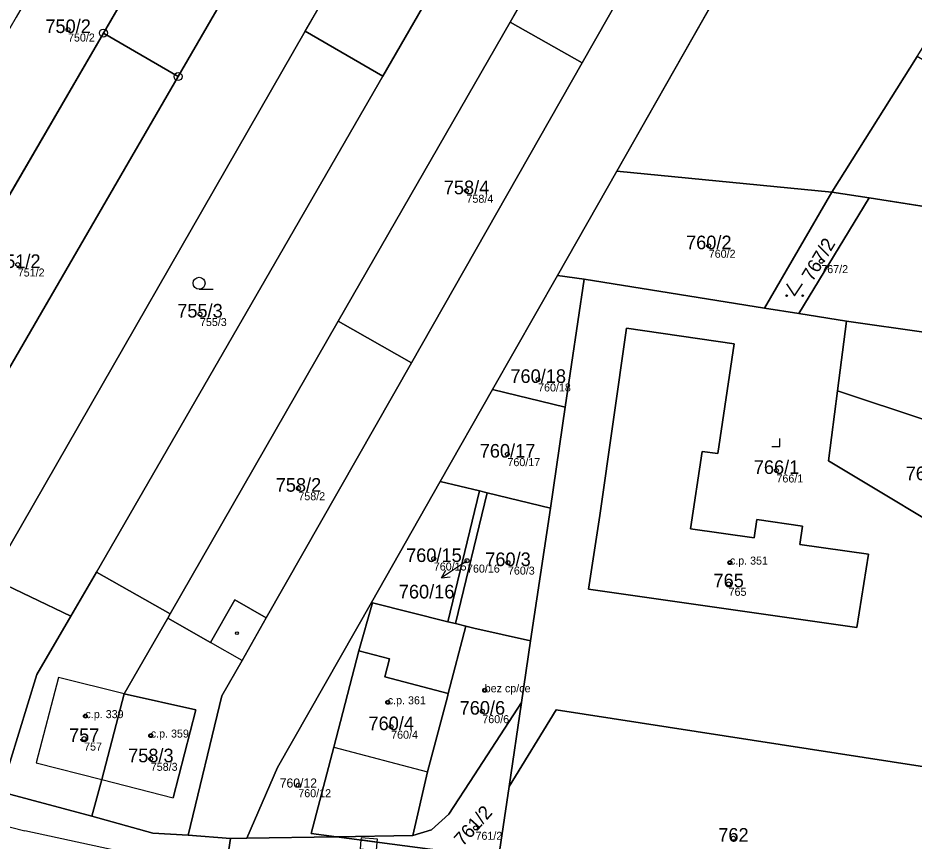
# Model space of a CAD drawing. Extents: x -603967 to -594699, y -1179315 to -1165625.
# Drawn here: x -598099.7 to -597987.7, y -1172272.3 to -1172169.5 of the extents above; entities that cross this region are included whole.
import ezdxf

# ---------------------------------------------------------------- set-up
doc = ezdxf.new("R2010")
doc.units = 0
for name, color, linetype in [('Definiční body', 7, 'Continuous'), ('Hranice parcel', 7, 'Continuous'), ('Parcelní čísla', 7, 'Continuous'), ('Polygon budovy', 7, 'Continuous'), ('Polygon parcely', 7, 'Continuous'), ('Pop  PČ popisy', 7, 'Continuous'), ('Vnitřní kresba', 7, 'Continuous'), ('Věcná břemena k části', 7, 'Continuous'), ('Značky bodu BP', 7, 'Continuous'), ('Značky budov', 7, 'Continuous'), ('Značky kultur', 7, 'Continuous')]:
    doc.layers.add(name, color=color, linetype=linetype)

msp = doc.modelspace()

# ---------------------------------------------------------------- linework, layer by layer
at = {"layer": 'Definiční body'}
for centre in [(-598093.44, -1172170.91994), (-598043.66, -1172191.05994), (-598013.39, -1172197.92994), (-598099.72, -1172200.26994), (-597999.33, -1172199.84994), (-598076.96, -1172206.45994), (-598034.71, -1172214.62994), (-598038.54, -1172223.95994), (-598004.93, -1172225.99994), (-598064.66, -1172228.21994), (-598047.74, -1172236.99994), (-598043.59, -1172237.25994), (-598038.48, -1172237.50994), (-598010.75, -1172237.49994), (-598010.91, -1172240.15994), (-598041.38, -1172253.44994), (-598053.49, -1172254.94994), (-598091.26, -1172256.67994), (-598041.68, -1172256.06994), (-598053.07, -1172258.00994), (-598091.43, -1172259.48994), (-598083.1, -1172259.10994), (-598083.1, -1172262.01994), (-598064.67, -1172265.31994), (-598042.53, -1172270.63994), (-598010.31, -1172271.93994)]:
    msp.add_circle(centre, 0.25, dxfattribs=at)
at = {"layer": 'Hranice parcel'}
for p, q in [((-598089.02, -1172171.35), (-598041.74, -1172089.99)), ((-598031.05, -1172092.86), (-598079.69, -1172176.78)), ((-598063.8, -1172171.13), (-598020.26, -1172095.37)), ((-598054.1, -1172176.74), (-598008.71, -1172098.13)), ((-598038.22, -1172169.98), (-597998.29, -1172100.64)), ((-598029.22, -1172175.08), (-597988.37, -1172103.28)), ((-598024.89, -1172188.58), (-597977.95, -1172106.04)), ((-598059.71, -1172207.33), (-598038.22, -1172169.98)), ((-598038.22, -1172169.98), (-598029.22, -1172175.08)), ((-598113.19, -1172212.94), (-598089.02, -1172171.35)), ((-598102.03, -1172237.66), (-598063.8, -1172171.13)), ((-598089.02, -1172171.35), (-598079.69, -1172176.78)), ((-598063.8, -1172171.13), (-598054.1, -1172176.74)), ((-597998, -1172191.21), (-597987.33, -1172174.26)), ((-598029.22, -1172175.08), (-598050.53, -1172212.53)), ((-598079.69, -1172176.78), (-598111.73, -1172232.07)), ((-598054.1, -1172176.74), (-598089.89, -1172238.69)), ((-598032.3, -1172201.62), (-598024.89, -1172188.58)), ((-598024.89, -1172188.58), (-597998, -1172191.21)), ((-598006.42, -1172205.7), (-597998, -1172191.21)), ((-597993.35, -1172191.94), (-597998, -1172191.21)), ((-598002.14, -1172206.39), (-597993.35, -1172191.94)), ((-597972.54, -1172195.22), (-597993.35, -1172191.94)), ((-598040.4, -1172215.87), (-598032.3, -1172201.62)), ((-598032.3, -1172201.62), (-598028.95, -1172202.1)), ((-598028.95, -1172202.1), (-598031.31, -1172218.07)), ((-598028.95, -1172202.1), (-598006.42, -1172205.7)), ((-598006.42, -1172205.7), (-598002.14, -1172206.39)), ((-598002.14, -1172206.39), (-597996.18, -1172207.34)), ((-598080.66, -1172243.92), (-598059.71, -1172207.33)), ((-598050.53, -1172212.53), (-598059.71, -1172207.33)), ((-597997.29, -1172216.06), (-597996.18, -1172207.34)), ((-598068.67, -1172244.4), (-598050.53, -1172212.53)), ((-598046.94, -1172227.36), (-598040.4, -1172215.87)), ((-598031.31, -1172218.07), (-598040.4, -1172215.87)), ((-597975.12, -1172223.43), (-597997.29, -1172216.06)), ((-598031.31, -1172218.07), (-598033.18, -1172230.68)), ((-598055.53, -1172242.48), (-598046.94, -1172227.36)), ((-598042.05, -1172228.54), (-598046.94, -1172227.36)), ((-598045.99, -1172244.88), (-598042.05, -1172228.54)), ((-598041.07, -1172228.78), (-598045.02, -1172245.12)), ((-598041.07, -1172228.78), (-598042.05, -1172228.54)), ((-598033.18, -1172230.68), (-598041.07, -1172228.78)), ((-598035.64, -1172247.28), (-598033.18, -1172230.68)), ((-598093.1, -1172244.2), (-598103.2, -1172239.38)), ((-598093.1, -1172244.2), (-598089.89, -1172238.69)), ((-598089.89, -1172238.69), (-598080.66, -1172243.92)), ((-598067.25, -1172263.09), (-598055.53, -1172242.48)), ((-598055.41, -1172242.51), (-598057.09, -1172248.51)), ((-598055.41, -1172242.51), (-598055.53, -1172242.48)), ((-598045.99, -1172244.88), (-598055.41, -1172242.51)), ((-598080.66, -1172243.92), (-598080.96, -1172244.44)), ((-598097.34, -1172251.48), (-598093.1, -1172244.2)), ((-598080.96, -1172244.44), (-598086.44, -1172253.89)), ((-598045.02, -1172245.12), (-598045.99, -1172244.88)), ((-598045.02, -1172245.12), (-598043.72, -1172245.45)), ((-598035.64, -1172247.28), (-598036.78, -1172254.99)), ((-598057.09, -1172248.51), (-598060.23, -1172260.57)), ((-598101.84, -1172266.14), (-598097.34, -1172251.48)), ((-598036.78, -1172254.99), (-598042.64, -1172264.03)), ((-598038.34, -1172265.49), (-598036.78, -1172254.99)), ((-598071.11, -1172271.92), (-598067.25, -1172263.09)), ((-598050.35, -1172271.6), (-598048.51, -1172263.64)), ((-598090.48, -1172269.19), (-598101.84, -1172266.14)), ((-598039.66, -1172274.43), (-598038.34, -1172265.49)), ((-598090.48, -1172269.19), (-598082.86, -1172271.28)), ((-598082.86, -1172271.28), (-598078.41, -1172271.53)), ((-598078.41, -1172271.53), (-598073.16, -1172271.95)), ((-598073.16, -1172271.95), (-598071.11, -1172271.92)), ((-598059.89, -1172271.75), (-598071.11, -1172271.92)), ((-598059.89, -1172271.75), (-598050.35, -1172271.6)), ((-598039.66, -1172274.43), (-598059.89, -1172271.75))]:
    msp.add_line(p, q, dxfattribs=at)
for points in [[(-598028.42, -1172240.8), (-598026.98, -1172231.6), (-598023.66, -1172208.21), (-598010.23, -1172210.19), (-598012.26, -1172223.89), (-598014.23, -1172223.6)], [(-597996.18, -1172207.34), (-597976.28, -1172210.18), (-597955.84, -1172213.01)], [(-597979.58, -1172236.11), (-597998.41, -1172224.79), (-597997.29, -1172216.06)], [(-598014.23, -1172223.6), (-598015.68, -1172233.3), (-598007.71, -1172234.42), (-598007.39, -1172232.13), (-598001.67, -1172232.94), (-598002, -1172235.22), (-597993.44, -1172236.43), (-597994.9, -1172245.61), (-598028.42, -1172240.8)], [(-598080.96, -1172244.44), (-598075.62, -1172247.48), (-598072.59, -1172242.16), (-598068.67, -1172244.4)], [(-598078.41, -1172271.53), (-598074.21, -1172254.14), (-598071.69, -1172249.71), (-598068.67, -1172244.4)], [(-598048.51, -1172263.64), (-598046.03, -1172254.27), (-598045.93, -1172253.84), (-598043.72, -1172245.45)], [(-598043.72, -1172245.45), (-598042.73, -1172245.7), (-598035.64, -1172247.28)], [(-598086.44, -1172253.89), (-598089.23, -1172264.61), (-598090.48, -1172269.19)], [(-597983.49, -1172263.46), (-598032.47, -1172255.88), (-598038.34, -1172265.49)], [(-598060.23, -1172260.57), (-598063.08, -1172271.35), (-598059.89, -1172271.75)], [(-598042.64, -1172264.03), (-598045.87, -1172268.94), (-598048.03, -1172270.89), (-598050.35, -1172271.6)], [(-598073.16, -1172271.95), (-598073.47, -1172274.19), (-598070.89, -1172276.93), (-598057.82, -1172275.89), (-598050.62, -1172276.09), (-598046.74, -1172275.42)]]:
    msp.add_lwpolyline(points, dxfattribs=at)
at = {"layer": 'Polygon budovy'}
for points in [[(-598026.98, -1172231.6), (-598028.42, -1172240.8), (-597994.9, -1172245.61), (-597993.44, -1172236.43), (-598002, -1172235.22), (-598001.67, -1172232.94), (-598007.39, -1172232.13), (-598007.71, -1172234.42), (-598015.68, -1172233.3), (-598014.23, -1172223.6), (-598012.26, -1172223.89), (-598010.23, -1172210.19), (-598023.66, -1172208.21)], [(-598043.72, -1172245.45), (-598045.93, -1172253.84), (-598046.03, -1172254.27), (-598048.51, -1172263.64), (-598050.35, -1172271.6), (-598048.03, -1172270.89), (-598045.87, -1172268.94), (-598042.64, -1172264.03), (-598036.78, -1172254.99), (-598035.64, -1172247.28), (-598042.73, -1172245.7)], [(-598057.09, -1172248.51), (-598060.23, -1172260.57), (-598048.51, -1172263.64), (-598046.03, -1172254.27), (-598045.93, -1172253.84), (-598053.84, -1172251.76), (-598053.28, -1172249.51)], [(-598094.64, -1172251.86), (-598097.43, -1172262.52), (-598089.23, -1172264.61), (-598086.44, -1172253.89)], [(-598089.23, -1172264.61), (-598080.32, -1172266.9), (-598077.46, -1172255.91), (-598086.44, -1172253.89)]]:
    msp.add_lwpolyline(points, close=True, dxfattribs=at)
at = {"layer": 'Polygon parcely'}
for points in [[(-598059.98, -1172100.28), (-598067.04, -1172112.5), (-598069.12, -1172116.1), (-598099.9, -1172169.36), (-598122.69, -1172208.79), (-598113.19, -1172212.94), (-598089.02, -1172171.35), (-598041.74, -1172089.99), (-598052.53, -1172087.39)], [(-598079.69, -1172176.78), (-598031.05, -1172092.86), (-598041.74, -1172089.99), (-598089.02, -1172171.35)], [(-598020.26, -1172095.37), (-598031.05, -1172092.86), (-598079.69, -1172176.78), (-598111.73, -1172232.07), (-598107.49, -1172234.38), (-598102.03, -1172237.66), (-598063.8, -1172171.13)], [(-598008.71, -1172098.13), (-598020.26, -1172095.37), (-598063.8, -1172171.13), (-598054.1, -1172176.74)], [(-598008.71, -1172098.13), (-598054.1, -1172176.74), (-598089.89, -1172238.69), (-598080.66, -1172243.92), (-598059.71, -1172207.33), (-598038.22, -1172169.98), (-597998.29, -1172100.64)], [(-598029.22, -1172175.08), (-597988.37, -1172103.28), (-597998.29, -1172100.64), (-598038.22, -1172169.98)], [(-597977.95, -1172106.04), (-597988.37, -1172103.28), (-598029.22, -1172175.08), (-598050.53, -1172212.53), (-598068.67, -1172244.4), (-598071.69, -1172249.71), (-598074.21, -1172254.14), (-598078.41, -1172271.53), (-598073.16, -1172271.95), (-598071.11, -1172271.92), (-598067.25, -1172263.09), (-598055.53, -1172242.48), (-598046.94, -1172227.36), (-598040.4, -1172215.87), (-598032.3, -1172201.62), (-598024.89, -1172188.58)], [(-597964.77, -1172138.05), (-597950.03, -1172113.6), (-597977.95, -1172106.04), (-598024.89, -1172188.58), (-597998, -1172191.21), (-597987.33, -1172174.26), (-597984.55, -1172169.83), (-597978.05, -1172159.64)], [(-598038.22, -1172169.98), (-598059.71, -1172207.33), (-598050.53, -1172212.53), (-598029.22, -1172175.08)], [(-598113.19, -1172212.94), (-598116.92, -1172219.55), (-598121.43, -1172227.12), (-598116.8, -1172229.12), (-598111.73, -1172232.07), (-598079.69, -1172176.78), (-598089.02, -1172171.35)], [(-598089.89, -1172238.69), (-598054.1, -1172176.74), (-598063.8, -1172171.13), (-598102.03, -1172237.66), (-598102.62, -1172238.6), (-598103.2, -1172239.38), (-598093.1, -1172244.2)], [(-597953.45, -1172191.33), (-597952.32, -1172182.74), (-597952.07, -1172180.42), (-597982.2, -1172177.32), (-597987.33, -1172174.26), (-597998, -1172191.21), (-597993.35, -1172191.94), (-597972.54, -1172195.22), (-597971.12, -1172183.2), (-597960.3, -1172184.48), (-597961.68, -1172196.64), (-597954.14, -1172197.63)], [(-598032.3, -1172201.62), (-598028.95, -1172202.1), (-598006.42, -1172205.7), (-597998, -1172191.21), (-598024.89, -1172188.58)], [(-597998, -1172191.21), (-598006.42, -1172205.7), (-598002.14, -1172206.39), (-597993.35, -1172191.94)], [(-597964.82, -1172208.2), (-597973.95, -1172207.12), (-597972.54, -1172195.22), (-597993.35, -1172191.94), (-598002.14, -1172206.39), (-597996.18, -1172207.34), (-597976.28, -1172210.18), (-597955.84, -1172213.01), (-597954.14, -1172197.63), (-597961.68, -1172196.64), (-597962.78, -1172205.93), (-597964.52, -1172205.72)], [(-598032.3, -1172201.62), (-598040.4, -1172215.87), (-598031.31, -1172218.07), (-598028.95, -1172202.1)], [(-598002.14, -1172206.39), (-598006.42, -1172205.7), (-598028.95, -1172202.1), (-598031.31, -1172218.07), (-598033.18, -1172230.68), (-598035.64, -1172247.28), (-598036.78, -1172254.99), (-598038.34, -1172265.49), (-598032.47, -1172255.88), (-597983.49, -1172263.46), (-597980.32, -1172241.29), (-597979.58, -1172236.11), (-597998.41, -1172224.79), (-597997.29, -1172216.06), (-597996.18, -1172207.34)], [(-598050.53, -1172212.53), (-598059.71, -1172207.33), (-598080.66, -1172243.92), (-598080.96, -1172244.44), (-598075.62, -1172247.48), (-598072.59, -1172242.16), (-598068.67, -1172244.4)], [(-598014.23, -1172223.6), (-598012.26, -1172223.89), (-598010.23, -1172210.19), (-598023.66, -1172208.21), (-598026.98, -1172231.6), (-598028.42, -1172240.8), (-597994.9, -1172245.61), (-597993.44, -1172236.43), (-598002, -1172235.22), (-598001.67, -1172232.94), (-598007.39, -1172232.13), (-598007.71, -1172234.42), (-598015.68, -1172233.3)], [(-598007.39, -1172232.13), (-598001.67, -1172232.94), (-598002, -1172235.22), (-597993.44, -1172236.43), (-597994.9, -1172245.61), (-598028.42, -1172240.8), (-598026.98, -1172231.6), (-598023.66, -1172208.21), (-598010.23, -1172210.19), (-598012.26, -1172223.89), (-598014.23, -1172223.6), (-598015.68, -1172233.3), (-598007.71, -1172234.42)], [(-597964.63, -1172224.94), (-597957.24, -1172226), (-597955.84, -1172213.01), (-597976.28, -1172210.18), (-597996.18, -1172207.34), (-597997.29, -1172216.06), (-597975.12, -1172223.43), (-597973.83, -1172214.15), (-597963.34, -1172215.61), (-597963.78, -1172218.82), (-597962.6, -1172218.99), (-597962.98, -1172221.7), (-597964.16, -1172221.58)], [(-598031.31, -1172218.07), (-598040.4, -1172215.87), (-598046.94, -1172227.36), (-598042.05, -1172228.54), (-598041.07, -1172228.78), (-598033.18, -1172230.68)], [(-597965.9, -1172234.19), (-597976.41, -1172232.72), (-597975.12, -1172223.43), (-597997.29, -1172216.06), (-597998.41, -1172224.79), (-597979.58, -1172236.11), (-597960.36, -1172247.21), (-597957.51, -1172228.47), (-597957.24, -1172226), (-597964.63, -1172224.94), (-597965.09, -1172228.26), (-597963.89, -1172228.43), (-597964.29, -1172231.15), (-597965.47, -1172231)], [(-598042.05, -1172228.54), (-598046.94, -1172227.36), (-598055.53, -1172242.48), (-598055.41, -1172242.51), (-598045.99, -1172244.88)], [(-598041.07, -1172228.78), (-598042.05, -1172228.54), (-598045.99, -1172244.88), (-598045.02, -1172245.12)], [(-598035.64, -1172247.28), (-598033.18, -1172230.68), (-598041.07, -1172228.78), (-598045.02, -1172245.12), (-598043.72, -1172245.45), (-598042.73, -1172245.7)], [(-598103.2, -1172239.38), (-598109.12, -1172248.1), (-598111.41, -1172258.89), (-598112.46, -1172263.54), (-598101.84, -1172266.14), (-598097.34, -1172251.48), (-598093.1, -1172244.2)], [(-598097.34, -1172251.48), (-598101.84, -1172266.14), (-598090.48, -1172269.19), (-598089.23, -1172264.61), (-598086.44, -1172253.89), (-598080.96, -1172244.44), (-598080.66, -1172243.92), (-598089.89, -1172238.69), (-598093.1, -1172244.2)], [(-598078.41, -1172271.53), (-598074.21, -1172254.14), (-598071.69, -1172249.71), (-598068.67, -1172244.4), (-598072.59, -1172242.16), (-598075.62, -1172247.48), (-598080.96, -1172244.44), (-598086.44, -1172253.89), (-598089.23, -1172264.61), (-598090.48, -1172269.19), (-598082.86, -1172271.28)], [(-598055.53, -1172242.48), (-598067.25, -1172263.09), (-598071.11, -1172271.92), (-598059.89, -1172271.75), (-598063.08, -1172271.35), (-598060.23, -1172260.57), (-598057.09, -1172248.51), (-598055.41, -1172242.51)], [(-598057.09, -1172248.51), (-598060.23, -1172260.57), (-598063.08, -1172271.35), (-598059.89, -1172271.75), (-598050.35, -1172271.6), (-598048.51, -1172263.64), (-598046.03, -1172254.27), (-598045.93, -1172253.84), (-598043.72, -1172245.45), (-598045.02, -1172245.12), (-598045.99, -1172244.88), (-598055.41, -1172242.51)], [(-598035.64, -1172247.28), (-598042.73, -1172245.7), (-598043.72, -1172245.45), (-598045.93, -1172253.84), (-598046.03, -1172254.27), (-598048.51, -1172263.64), (-598050.35, -1172271.6), (-598048.03, -1172270.89), (-598045.87, -1172268.94), (-598042.64, -1172264.03), (-598036.78, -1172254.99)], [(-598045.87, -1172268.94), (-598048.03, -1172270.89), (-598050.35, -1172271.6), (-598059.89, -1172271.75), (-598039.66, -1172274.43), (-598038.34, -1172265.49), (-598036.78, -1172254.99), (-598042.64, -1172264.03)], [(-598038.34, -1172265.49), (-598039.66, -1172274.43), (-598039.95, -1172276.37), (-598031.69, -1172277.53), (-597986.41, -1172283.87), (-597983.49, -1172263.46), (-598032.47, -1172255.88)], [(-598059.89, -1172271.75), (-598071.11, -1172271.92), (-598073.16, -1172271.95), (-598073.47, -1172274.19), (-598070.89, -1172276.93), (-598057.82, -1172275.89), (-598050.62, -1172276.09), (-598046.74, -1172275.42), (-598039.95, -1172276.37), (-598039.66, -1172274.43)]]:
    msp.add_lwpolyline(points, close=True, dxfattribs=at)
msp.add_lwpolyline([(-598073.47, -1172274.19), (-598073.16, -1172271.95), (-598078.41, -1172271.53), (-598082.86, -1172271.28), (-598090.48, -1172269.19), (-598101.84, -1172266.14), (-598112.46, -1172263.54), (-598124.03, -1172260.73), (-598134.74, -1172258.12), (-598145.44, -1172255.45), (-598155.65, -1172252.91), (-598166.74, -1172250.14), (-598187.86, -1172244.77), (-598198.53, -1172242.16), (-598202.31, -1172241.23), (-598217.72, -1172237.46), (-598219.87, -1172236.93), (-598230.62, -1172234.12), (-598236.36, -1172232.63), (-598242.25, -1172231.09), (-598247.86, -1172229.53), (-598251.97, -1172228.39)], dxfattribs=at)
at = {"layer": 'Pop  PČ popisy'}
for p, q in [((-598043.59, -1172237.26), (-598044.3, -1172237.74)), ((-598044.3, -1172237.74), (-598046.788, -1172239.418)), ((-598046.788, -1172239.418), (-598046.238, -1172238.443)), ((-598046.788, -1172239.418), (-598045.678, -1172239.273))]:
    msp.add_line(p, q, dxfattribs=at)
at = {"layer": 'Vnitřní kresba'}
for p, q in [((-598071.69, -1172249.71), (-598075.62, -1172247.48)), ((-598057.09, -1172248.51), (-598053.28, -1172249.51)), ((-598053.28, -1172249.51), (-598053.84, -1172251.76)), ((-598094.64, -1172251.86), (-598097.43, -1172262.52)), ((-598086.44, -1172253.89), (-598094.64, -1172251.86)), ((-598053.84, -1172251.76), (-598045.93, -1172253.84)), ((-598086.44, -1172253.89), (-598077.46, -1172255.91)), ((-598077.46, -1172255.91), (-598080.32, -1172266.9)), ((-598060.23, -1172260.57), (-598048.51, -1172263.64)), ((-598134.44, -1172261.99), (-598098.82, -1172271)), ((-598097.43, -1172262.52), (-598089.23, -1172264.61)), ((-598089.23, -1172264.61), (-598080.32, -1172266.9)), ((-598087.69, -1172273.44), (-598098.82, -1172271))]:
    msp.add_line(p, q, dxfattribs=at)
at = {"layer": 'Věcná břemena k části'}
for points in [[(-598056.84, -1172272.15), (-598054.82, -1172272.42), (-598054.78, -1172272.07), (-598056.81, -1172271.87)], [(-598054.92, -1172273.45), (-598054.82, -1172272.42), (-598056.84, -1172272.15), (-598056.95, -1172273.25)]]:
    msp.add_lwpolyline(points, close=True, dxfattribs=at)
at = {"layer": 'Značky bodu BP'}
for centre, radius in [((-598089.02, -1172171.34988), 0.5), ((-598089.02, -1172171.34988), 0.0303), ((-598079.69, -1172176.77988), 0.5), ((-598079.69, -1172176.77988), 0.0303)]:
    msp.add_circle(centre, radius, dxfattribs=at)
at = {"layer": 'Značky budov'}
for centre in [(-598010.7568, -1172237.49916), (-598072.3368, -1172246.31916), (-598041.3868, -1172253.44916), (-598053.4968, -1172254.94916), (-598091.2668, -1172256.67916), (-598083.1068, -1172259.10916)]:
    msp.add_circle(centre, 0.175, dxfattribs=at)
at = {"layer": 'Značky kultur'}
for p, q in [((-598077.063, -1172203.36), (-598075.313, -1172203.36)), ((-598004.5, -1172222.99), (-598004.5, -1172221.99)), ((-598005.501, -1172222.99), (-598004.5, -1172222.99))]:
    msp.add_line(p, q, dxfattribs=at)
msp.add_lwpolyline([(-598003.66, -1172202.659), (-598002.66, -1172204.16), (-598001.66, -1172202.659)], dxfattribs=at)
for centre, radius in [((-598077.06286, -1172202.60981), 0.75), ((-598003.66, -1172204.15946), 0.1), ((-598001.66, -1172204.15946), 0.1)]:
    msp.add_circle(centre, radius, dxfattribs=at)

# ---------------------------------------------------------------- texts
at = {"layer": 'Definiční body'}
for s, p in [('750/2', (-598093.44, -1172172.409)), ('758/4', (-598043.66, -1172192.549)), ('760/2', (-598013.39, -1172199.419)), ('767/2', (-597999.33, -1172201.339)), ('751/2', (-598099.72, -1172201.759)), ('755/3', (-598076.96, -1172207.949)), ('760/18', (-598034.71, -1172216.119)), ('760/17', (-598038.54, -1172225.449)), ('766/1', (-598004.93, -1172227.489)), ('758/2', (-598064.66, -1172229.709)), ('760/15', (-598047.74, -1172238.489)), ('c.p. 351', (-598010.75, -1172237.75)), ('760/16', (-598043.59, -1172238.749)), ('760/3', (-598038.48, -1172238.999)), ('765', (-598010.91, -1172241.649)), ('bez cp/ce', (-598041.38, -1172253.7)), ('c.p. 361', (-598053.49, -1172255.2)), ('c.p. 339', (-598091.26, -1172256.93)), ('760/6', (-598041.68, -1172257.559)), ('c.p. 359', (-598083.1, -1172259.36)), ('760/4', (-598053.07, -1172259.499)), ('757', (-598091.43, -1172260.979)), ('758/3', (-598083.1, -1172263.509)), ('760/12', (-598064.67, -1172266.809)), ('761/2', (-598042.53, -1172272.129))]:
    msp.add_text(s, height=0.999996, dxfattribs=at).set_placement(p)
at = {"layer": 'Parcelní čísla'}
for s, height, p in [('750/2', 1.699998, (-598096.276, -1172171.345)), ('758/4', 1.699998, (-598046.496, -1172191.485)), ('760/2', 1.699998, (-598016.226, -1172198.355)), ('751/2', 1.699998, (-598102.556, -1172200.695)), ('755/3', 1.699998, (-598079.796, -1172206.885)), ('760/18', 1.699998, (-598038.176, -1172215.055)), ('760/17', 1.699998, (-598042.006, -1172224.385)), ('766/1', 1.699998, (-598007.766, -1172226.425)), ('766/2', 1.699998, (-597988.786, -1172227.205)), ('758/2', 1.699998, (-598067.496, -1172228.645)), ('760/15', 1.699998, (-598051.206, -1172237.425)), ('760/3', 1.699998, (-598041.316, -1172237.935)), ('765', 1.699998, (-598012.8, -1172240.585)), ('760/16', 1.699998, (-598052.116, -1172241.975)), ('760/6', 1.699998, (-598044.516, -1172256.495)), ('760/4', 1.699998, (-598055.906, -1172258.435)), ('757', 1.699998, (-598093.32, -1172259.915)), ('758/3', 1.699998, (-598085.936, -1172262.445)), ('760/12', 1.138998, (-598066.992, -1172265.604)), ('762', 1.699998, (-598012.2, -1172272.365))]:
    msp.add_text(s, height=height, dxfattribs=at).set_placement(p)
for s, rotation, p in [('767/2', 59, (-598000.426, -1172202.499)), ('761/2', 48, (-598044.111, -1172273.032))]:
    msp.add_text(s, height=1.699998, rotation=rotation, dxfattribs=at).set_placement(p)

doc.saveas('drawing.dxf')
